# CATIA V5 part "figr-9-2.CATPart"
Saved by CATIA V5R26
Part number: Part1
Bounding box of the stored display mesh (mm): x -25 to 69.61, y -139.735 to 0, z 0 to 45
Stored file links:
  D:\_Deepak\CATIA\CATIA V5-6R2016_Deepak\Resources\Part files\Partfiles\c09_catia_v5_6r2016_prt\figr-9-2.CATPart
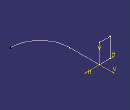
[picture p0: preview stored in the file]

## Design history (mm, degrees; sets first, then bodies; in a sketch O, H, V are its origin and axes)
Body1 (main body)
  Sketch1 on xy-plane, origin (0, 0, 0), H (1, 0, 0), V (0, 1, 0)
    line L1 (0, 0) -> (0, -70.1255)
    arc A1 centre (69.6095, -70.1255) radius 69.6095 from (0, -70.1255) to (69.6095, -139.7351) ccw
    vertical: L1 V
    tangency: A1 L1
  Sketch2 on zx-plane, origin (0, 0, 0), H (-1, 0, 0), V (0, 0, 1)
    point P1 (0, 0)
    line L1 (0, 0) -> (25, 0)
    line L2 (25, 0) -> (25, 45)
    line L3 (25, 45) -> (0, 45)
    line L4 (0, 45) -> (0, 0)
    length L3 = 25
    length L2 = 45
    coincidence: P1 H, P1 O
    horizontal: L1 H, L3 H
    vertical: L2 V, L4 V
  Rib1: profile Sketch2, centre curve Sketch1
